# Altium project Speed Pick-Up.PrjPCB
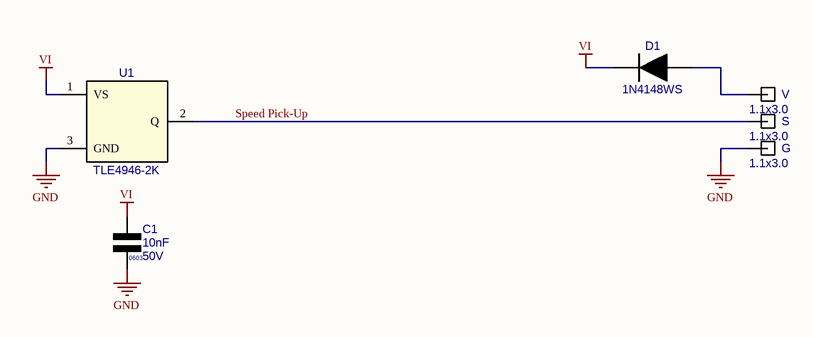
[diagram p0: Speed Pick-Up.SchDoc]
Version: 01.00; SCH_Title: Speed Pick-Up; SCH_SheetTotal: 1; SCH_Reviewed: DG; SCH_QA: -; SCH_Number: -; SCH_FILENAME: Speed Pick-Up.SCH; SCH_ECR: -; SCH_DRAWN: DG; SCH_DocRev: 01; SCH_Date: 18/08/2015; SCH_CM: -; SCH_Approved: DG; PCB_TITLE: Speed Pick-Up PCB; PCB_Plot_File_[Assy]: Speed Pick-Up [Assy]; PCB_Plot_File: Speed Pick-Up [Panel]; PCB_ECRNo: -; PCB_Drawn: EDM; PCB_Drawing_Number: -; PCB_DocRevision: 01; PCB_Company Name: AGRIGEL
1 sheet, 6 parts. Net scope: global (net labels, ports and power ports of the same name join across sheets).
Board files: Speed Pick-Up [Assy].PcbDoc, Speed Pick-Up [Panel].PcbDoc, Speed Pick-Up.PcbDoc

## Sheet Speed Pick-Up.SchDoc: #
size A3; ApprovedBy: #; DrawnBy: #; DocumentNumber: 1; Revision: #; SheetNumber: 1; SheetTotal: 1; DocumentRevision: #; Reviewed: #; QA: #; CM: #; ECR: #; PageSetup: Record=PageOptions¦CenterHorizontal=True¦CenterVertical=True¦PrintScale=0.97¦XCorrection=1.00¦YCorrection=1.00¦PrintKind=1¦BorderSize=5000000¦LeftOffset=0¦BottomOffset=0¦Orientation=2¦PaperLength=1000¦PaperWidth=1000¦Scale=100¦PaperSource=7¦PrintQuality=-4¦MediaType=1¦DitherType=10¦PaperKind=A3¦PrintScaleMode=1

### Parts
C1  value 10nF  Voltage: 50V  Text1: 0603  [CAPC0603X85N]  (hidden comment: 10nF_C0603_50V_10%_X7R)
D1  1N4148WS  [SOD323]
G  Part Number: 1.1x3.0  [PAD-SMD-1.1x3.0mm Rect]  (hidden comment: Pad-SMD-1.1x3.0mm-H_Rectangle)
S  Part Number: 1.1x3.0  [PAD-SMD-1.1x3.0mm Rect]  (hidden comment: Pad-SMD-1.1x3.0mm-H_Rectangle)
U1  TLE4946-2K  [SOT23]
V  Part Number: 1.1x3.0  [PAD-SMD-1.1x3.0mm Rect]  (hidden comment: Pad-SMD-1.1x3.0mm-H_Rectangle)

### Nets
GND: C1.2 G.1 U1.3(GND)
VI: C1.1 D1.1(C) U1.1(VS)
Speed Pick-Up: S.1 U1.2(Q)
NetD1_2: D1.2(A) V.1

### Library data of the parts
C1 = 10nF_0603N_50V_10%_X7R_V: Cap Ceramic X7R; Manufacturer: Various; Part Number: 10nF 0603 50V 10% X7R; Board Tech: SMD; Tol: 10%; Reutech PN: 5910-CA-0402
D1 = 1N4148WS_SOD323_H: Diode Fast Switching Surface Mount; Manufacturer: Diodes; Board Tech: SMD
G S V = Pad-SMD-1.1x3.0mm-H_Rectangle: Surface Mount Pad 1.1x3.0mm Rectangle; Manufacturer: Generic; Board Tech: SMD; Value: SMD 1.1x3.0mm Rectangle
U1 = TLE4946-2K_SOT23: IC Hall Effect Latch; Manufacturer: Infineon; Board Tech: SMD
